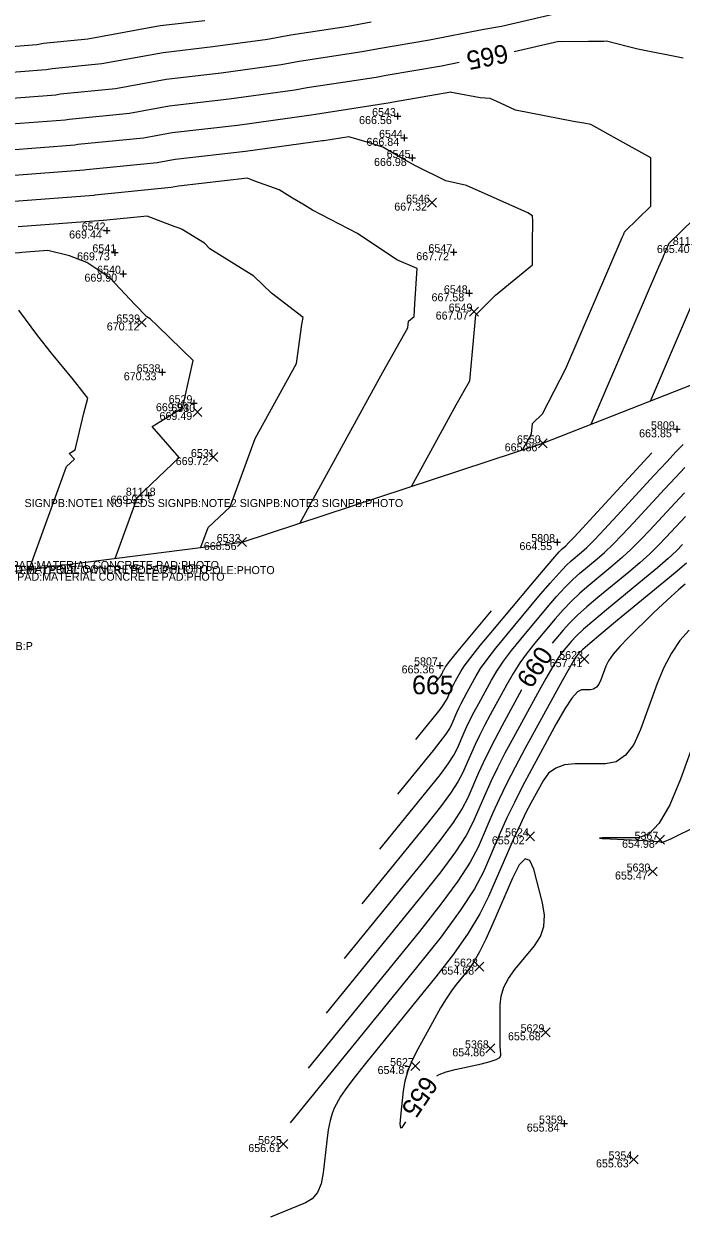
# Model space of a CAD drawing. Extents: x 2129350 to 2137777, y 657588 to 659885.
# Drawn here: x 2132634.9 to 2132733.5, y 658234.1 to 658413.1 of the extents above; entities that cross this region are included whole.
import ezdxf

# ---------------------------------------------------------------- set-up
doc = ezdxf.new("R2010")
doc.units = 0
for name, color, linetype in [('DT_X_Contour_Major', 7, 'Continuous'), ('DT_X_Contour_Minor', 7, 'Continuous'), ('DT_X_TIN_Hull', 7, 'Continuous'), ('SV_X_Random_Point', 7, 'Continuous'), ('SV_X_Shot_Marker', 7, 'Continuous'), ('SV_X_Text_Comment', 7, 'Continuous'), ('SV_X_Text_Elevation', 7, 'Continuous'), ('SV_X_Text_Name', 7, 'Continuous')]:
    doc.layers.add(name, color=color, linetype=linetype)

msp = doc.modelspace()

# ---------------------------------------------------------------- linework, layer by layer
at = {"layer": 'DT_X_Contour_Major'}
for points in [[(2132733.81, 658407.96), (2132726.98, 658409.33), (2132725.6, 658409.66), (2132722.3, 658410.53), (2132721.9, 658410.49), (2132719.6, 658410.48), (2132715.59, 658410.45), (2132715.13, 658410.49), (2132708.45, 658408.95)], [(2132700.21, 658407.32), (2132697.53, 658406.8), (2132689.22, 658405.37), (2132687.73, 658405.1), (2132677.4, 658403.51), (2132675.56, 658403.17), (2132665.7, 658401.82), (2132656.7, 658400.79), (2132650.73, 658399.69), (2132641.7, 658398.8), (2132641.1, 658398.69), (2132631.66, 658397.97), (2132623.7, 658396.59), (2132614.4, 658395.99), (2132605.99, 658395.57), (2132601.12, 658394.71)], [(2132720.02, 658353.06), (2132730.17, 658376.69), (2132730.64, 658377.78), (2132730.79, 658378.14), (2132730.92, 658378.42), (2132731, 658378.62), (2132731.05, 658378.74), (2132731.14, 658378.94), (2132731.18, 658379.03), (2132731.22, 658379.13), (2132731.27, 658379.25), (2132731.33, 658379.38), (2132731.49, 658379.76), (2132731.54, 658379.89), (2132731.58, 658379.98), (2132731.61, 658380.05), (2132731.63, 658380.08), (2132731.67, 658380.17), (2132737.35, 658385.73)], [(2132648.58, 658332.95), (2132651.92, 658342.14), (2132658.21, 658348.06), (2132654.14, 658352.71), (2132658.69, 658355.55), (2132658.89, 658356.35), (2132659.12, 658357.46), (2132660.29, 658362.61), (2132655, 658367.76), (2132653.85, 658368.86), (2132653.35, 658369.17), (2132651.55, 658371.01), (2132647.83, 658374.97), (2132647.18, 658375.42), (2132644.32, 658377.35), (2132641.75, 658378.31), (2132638.48, 658379.15), (2132634.61, 658378.85), (2132634.23, 658378.79), (2132620.68, 658377.91), (2132608.42, 658377.3), (2132606.2, 658376.91), (2132603.7, 658376.78)], [(2132734.14, 658339.24), (2132731.27, 658336.11), (2132730.11, 658334.91), (2132728.78, 658333.64), (2132727.29, 658332.3), (2132725.63, 658330.9), (2132720.98, 658327.07), (2132719.35, 658325.69), (2132717.95, 658324.42), (2132716.77, 658323.25), (2132715.82, 658322.2), (2132714.17, 658320.22)], [(2132696.36, 658313.97), (2132697.16, 658314.97), (2132697.32, 658315.16), (2132697.44, 658315.33), (2132697.53, 658315.47), (2132697.59, 658315.58), (2132697.7, 658315.83), (2132697.74, 658315.93), (2132697.8, 658316.04), (2132697.86, 658316.16), (2132697.93, 658316.29), (2132698.13, 658316.66), (2132698.33, 658316.94), (2132698.76, 658317.48), (2132699.42, 658318.29), (2132700.32, 658319.37), (2132705.07, 658325.06)], [(2132709.56, 658313.21), (2132706.6, 658307.79), (2132705.53, 658305.78), (2132704.59, 658303.95), (2132703.78, 658302.29), (2132703.11, 658300.8), (2132701.49, 658297.04), (2132700.63, 658295.41), (2132699.28, 658293.33), (2132697.42, 658290.81), (2132695.07, 658287.84), (2132682.92, 658272.93)], [(2132737.66, 658311.57), (2132733.4, 658299.82), (2132731.8, 658295.96), (2132730.21, 658293.21), (2132728.63, 658291.56), (2132727.05, 658291.01), (2132722.85, 658291.02), (2132721.66, 658291.01), (2132721.27, 658290.98), (2132721.67, 658290.93), (2132722.86, 658290.87), (2132727.09, 658290.66), (2132728.49, 658290.59), (2132729.51, 658290.53), (2132730.15, 658290.48), (2132730.41, 658290.44), (2132730.62, 658290.35), (2132730.99, 658290.47), (2132731.93, 658290.89), (2132733.45, 658291.61), (2132735.56, 658292.64)], [(2132711.38, 658286.31), (2132710.81, 658287.65), (2132710.09, 658287.88), (2132709.21, 658286.99), (2132708.19, 658284.99), (2132705.24, 658278.18), (2132704.19, 658275.83), (2132703.24, 658273.91), (2132702.38, 658272.42), (2132701.63, 658271.34), (2132699.76, 658269.05), (2132699.03, 658268.08), (2132698.24, 658266.9), (2132697.4, 658265.51), (2132696.49, 658263.91), (2132693.99, 658259.35), (2132693.15, 658257.67), (2132692.51, 658256.07), (2132692.06, 658254.53), (2132691.8, 658253.07), (2132691.37, 658249.25), (2132691.29, 658248.1), (2132691.37, 658247.54), (2132691.62, 658247.57), (2132692.03, 658248.17), (2132692.19, 658248.45)], [(2132696.84, 658255.36), (2132697.19, 658255.55), (2132698.24, 658255.94), (2132699.59, 658256.29), (2132703.55, 658257.15), (2132704.84, 658257.47), (2132705.76, 658257.79), (2132706.3, 658258.11), (2132706.46, 658258.42), (2132706.39, 658259.26), (2132706.36, 658259.69), (2132706.35, 658260.38), (2132706.34, 658261.31), (2132706.34, 658262.49), (2132706.36, 658265.98), (2132706.5, 658267.29), (2132706.92, 658268.61), (2132707.61, 658269.93), (2132708.57, 658271.26), (2132711.5, 658274.81), (2132712.4, 658276.21), (2132712.9, 658277.75), (2132713, 658279.43), (2132712.7, 658281.26), (2132711.38, 658286.31)]]:
    msp.add_lwpolyline(points, dxfattribs=at)
at = {"layer": 'DT_X_Contour_Minor'}
for points in [[(2132686.97, 658413.36), (2132683.52, 658412.74), (2132674.93, 658411.42), (2132671.43, 658410.78), (2132663.25, 658409.66), (2132655.79, 658408.8), (2132646.57, 658407.11), (2132639.12, 658406.37), (2132638.25, 658406.21), (2132630.49, 658405.62), (2132619.48, 658403.71), (2132611.89, 658403.22), (2132605.01, 658402.87), (2132595.15, 658401.13), (2132587.26, 658400.74), (2132586.04, 658400.5), (2132584.46, 658400.12), (2132577.38, 658399.83), (2132558.94, 658412.26), (2132549.46, 658417.46)], [(2132714.5, 658414.57), (2132706.55, 658412.74), (2132703.92, 658412.27), (2132695.72, 658410.68), (2132688.1, 658409.36), (2132685.62, 658408.92), (2132676.17, 658407.46), (2132673.49, 658406.97), (2132664.48, 658405.74), (2132656.25, 658404.8), (2132648.65, 658403.4), (2132640.41, 658402.58), (2132639.67, 658402.45), (2132631.07, 658401.8), (2132621.59, 658400.15), (2132613.14, 658399.61), (2132605.5, 658399.22), (2132596.73, 658397.67), (2132587.92, 658397.23), (2132586.82, 658397.02), (2132585.4, 658396.68), (2132577.49, 658396.35), (2132556.9, 658410.23), (2132546.31, 658416.04)], [(2132662.03, 658413.58), (2132655.34, 658412.81), (2132644.48, 658410.82), (2132637.83, 658410.16), (2132636.83, 658409.97), (2132629.9, 658409.45), (2132617.38, 658407.27), (2132610.63, 658406.84), (2132604.53, 658406.53), (2132593.57, 658404.59), (2132586.59, 658404.24), (2132585.26, 658403.98), (2132583.52, 658403.57), (2132577.26, 658403.31), (2132560.98, 658414.29)], [(2132709.71, 658349.21), (2132710.75, 658351.1), (2132711.06, 658351.65), (2132711.2, 658353.17), (2132712.68, 658354.65), (2132716.22, 658361.42), (2132724.67, 658381.09), (2132724.79, 658381.36), (2132724.83, 658381.46), (2132724.86, 658381.53), (2132724.89, 658381.58), (2132724.9, 658381.61), (2132724.92, 658381.66), (2132724.93, 658381.68), (2132724.94, 658381.71), (2132724.95, 658381.74), (2132724.97, 658381.77), (2132725.01, 658381.87), (2132725.02, 658381.9), (2132725.04, 658381.93), (2132725.04, 658381.95), (2132725.05, 658381.95), (2132725.06, 658381.98), (2132728.94, 658385.77), (2132728.94, 658388.15), (2132728.94, 658393.01), (2132724.35, 658395.57), (2132719.96, 658398.05), (2132718.92, 658398.21), (2132717.35, 658398.46), (2132708.67, 658400.16), (2132706.38, 658401.24), (2132704.87, 658401.91), (2132703.34, 658402.04), (2132699.62, 658402.72), (2132699.1, 658402.82), (2132698.96, 658402.86), (2132690.34, 658401.37), (2132689.83, 658401.28), (2132678.64, 658399.55), (2132677.62, 658399.37), (2132666.93, 658397.9), (2132657.16, 658396.78), (2132652.82, 658395.99), (2132642.98, 658395.01), (2132642.52, 658394.92), (2132632.25, 658394.15)], [(2132693.02, 658343.74), (2132699.75, 658355.98), (2132701.78, 658359.58), (2132702.69, 658369.46), (2132705.66, 658372.44), (2132711.18, 658377), (2132711.2, 658377.63), (2132711.2, 658380.22), (2132711.23, 658383.54), (2132711.22, 658384.34), (2132710.5, 658384.77), (2132701.32, 658388.88), (2132698.19, 658389.59), (2132693.64, 658391.85), (2132692.2, 658392.62), (2132691.82, 658392.84), (2132688.74, 658394.65), (2132686.37, 658395.39), (2132683.62, 658396.18), (2132679.87, 658395.6), (2132679.69, 658395.56), (2132668.15, 658393.99), (2132657.61, 658392.78), (2132654.9, 658392.28), (2132644.27, 658391.22), (2132643.94, 658391.16), (2132632.84, 658390.33)], [(2132676.33, 658338.26), (2132688.76, 658360.87), (2132692.5, 658367.51), (2132692.6, 658368.55), (2132693.45, 658369.23), (2132693.52, 658371.12), (2132693.9, 658376.44), (2132690.83, 658377.75), (2132684.92, 658381.69), (2132678.21, 658385.19), (2132676.74, 658386.06), (2132675.19, 658386.97), (2132673.21, 658388.21), (2132669.56, 658389.52), (2132668.43, 658389.96), (2132658.07, 658388.77), (2132656.98, 658388.57), (2132645.56, 658387.44), (2132645.37, 658387.4), (2132633.43, 658386.5)], [(2132661.46, 658334.61), (2132662.54, 658337.58), (2132665.84, 658340.68), (2132669.59, 658350.94), (2132675.77, 658362.17), (2132676.6, 658368.01), (2132676.79, 658369.08), (2132672.06, 658372.72), (2132669.39, 658375.27), (2132662.78, 658379.4), (2132661.99, 658380.21), (2132658.65, 658382.26), (2132658.34, 658382.45), (2132657.46, 658382.75), (2132653.38, 658384.3), (2132646.84, 658383.65), (2132646.79, 658383.64), (2132634.02, 658382.68)], [(2132728.9, 658356.55), (2132735.67, 658372.3)], [(2132635.7, 658331.3), (2132641.3, 658346.71), (2132642.47, 658347.81), (2132641.71, 658348.68), (2132642.57, 658349.21), (2132643.91, 658354.74), (2132644.51, 658356.99), (2132642.35, 658359.71), (2132639.06, 658363.74), (2132636.97, 658366.32), (2132634.12, 658370.2)], [(2132690.98, 658297.56), (2132696.33, 658304.11), (2132697.36, 658305.42), (2132698.18, 658306.53), (2132698.77, 658307.45), (2132699.15, 658308.16), (2132699.86, 658309.81), (2132700.16, 658310.47), (2132700.52, 658311.2), (2132700.93, 658312.01), (2132701.4, 658312.89), (2132702.74, 658315.34), (2132703.4, 658316.41), (2132704.39, 658317.8), (2132705.71, 658319.49), (2132707.35, 658321.5), (2132712.17, 658327.26), (2132713.83, 658329.21), (2132715.18, 658330.75), (2132716.23, 658331.86), (2132716.98, 658332.56), (2132718.56, 658333.86), (2132719.34, 658334.57), (2132720.49, 658335.73), (2132722.01, 658337.33), (2132723.91, 658339.37), (2132729.46, 658345.41), (2132731.33, 658347.43), (2132732.77, 658348.97), (2132733.79, 658350.02)], [(2132693.67, 658305.77), (2132696.74, 658309.54), (2132697.34, 658310.29), (2132697.81, 658310.93), (2132698.15, 658311.46), (2132698.37, 658311.87), (2132698.78, 658312.82), (2132698.95, 658313.2), (2132699.16, 658313.62), (2132699.39, 658314.08), (2132699.67, 658314.59), (2132700.43, 658316), (2132700.95, 658316.78), (2132701.93, 658318.07), (2132703.37, 658319.86), (2132705.27, 658322.15), (2132710.96, 658328.95), (2132712.85, 658331.2), (2132714.26, 658332.85), (2132715.19, 658333.92), (2132715.64, 658334.39), (2132716.2, 658334.85), (2132716.62, 658335.26), (2132717.45, 658336.13), (2132718.7, 658337.46), (2132720.36, 658339.27), (2132729.09, 658348.76)], [(2132688.29, 658289.35), (2132695.91, 658298.69), (2132697.38, 658300.55), (2132698.54, 658302.13), (2132699.39, 658303.43), (2132699.93, 658304.46), (2132700.95, 658306.81), (2132701.37, 658307.74), (2132701.87, 658308.79), (2132702.46, 658309.93), (2132703.13, 658311.19), (2132705.04, 658314.68), (2132705.85, 658316.04), (2132706.85, 658317.53), (2132708.05, 658319.13), (2132709.43, 658320.84), (2132713.39, 658325.57), (2132714.81, 658327.23), (2132716.1, 658328.64), (2132717.27, 658329.8), (2132718.31, 658330.73), (2132720.92, 658332.87), (2132721.99, 658333.82), (2132723.25, 658335.03), (2132724.71, 658336.52), (2132726.36, 658338.28), (2132731.02, 658343.35), (2132732.65, 658345.1), (2132734.05, 658346.56)], [(2132733.98, 658342.78), (2132732.58, 658341.29), (2132728.82, 658337.2), (2132727.41, 658335.72), (2132726.02, 658334.34), (2132724.64, 658333.06), (2132723.27, 658331.89), (2132719.65, 658328.9), (2132718.31, 658327.75), (2132717.03, 658326.53), (2132715.79, 658325.24), (2132714.61, 658323.89), (2132711.51, 658320.19), (2132710.38, 658318.76), (2132709.31, 658317.26), (2132708.3, 658315.68), (2132707.34, 658314.02), (2132704.87, 658309.49), (2132704, 658307.86), (2132703.23, 658306.37), (2132702.58, 658305.02), (2132702.03, 658303.8), (2132700.71, 658300.75), (2132700.01, 658299.42), (2132698.91, 658297.73), (2132697.4, 658295.68), (2132695.49, 658293.26), (2132685.6, 658281.14)], [(2132733.72, 658335.03), (2132732.81, 658334.1), (2132731.55, 658332.94), (2132729.94, 658331.55), (2132727.99, 658329.91), (2132722.32, 658325.24), (2132720.39, 658323.63), (2132718.87, 658322.31), (2132717.76, 658321.27), (2132717.04, 658320.51), (2132715.67, 658318.88), (2132715.05, 658318.03), (2132714.23, 658316.72), (2132713.19, 658314.94), (2132711.94, 658312.69), (2132708.34, 658306.09), (2132707.07, 658303.71), (2132705.95, 658301.53), (2132704.99, 658299.56), (2132704.19, 658297.79), (2132702.27, 658293.34), (2132701.25, 658291.4), (2132699.64, 658288.93), (2132697.44, 658285.94), (2132694.65, 658282.41), (2132680.23, 658264.72)], [(2132734.31, 658332.25), (2132732.59, 658330.79), (2132730.35, 658328.92), (2132723.66, 658323.41), (2132721.44, 658321.58), (2132719.8, 658320.2), (2132718.74, 658319.28), (2132718.26, 658318.83), (2132717.75, 658318.22), (2132717.39, 658317.67), (2132716.69, 658316.45), (2132715.64, 658314.57), (2132714.24, 658312.03), (2132710.07, 658304.39), (2132708.6, 658301.63), (2132707.31, 658299.12), (2132706.2, 658296.83), (2132705.27, 658294.78), (2132703.05, 658289.63), (2132701.87, 658287.39), (2132700.01, 658284.54), (2132697.46, 658281.07), (2132694.23, 658276.99), (2132677.54, 658256.51)], [(2132734.1, 658329.09), (2132733.1, 658328.24), (2132731.98, 658327.23), (2132730.74, 658326.07), (2132729.37, 658324.76), (2132725.57, 658321.05), (2132724.29, 658319.74), (2132723.3, 658318.59), (2132722.6, 658317.6), (2132722.18, 658316.76), (2132721.45, 658314.75), (2132721.14, 658314.09), (2132720.78, 658313.62), (2132720.37, 658313.33), (2132719.9, 658313.24), (2132718.57, 658313.24), (2132717.95, 658312.92), (2132717.12, 658311.96), (2132716.06, 658310.36), (2132714.77, 658308.12), (2132711.05, 658301.29), (2132709.71, 658298.78), (2132708.48, 658296.35), (2132707.36, 658294.02), (2132706.36, 658291.78), (2132703.83, 658285.92), (2132702.49, 658283.38), (2132700.37, 658280.14), (2132697.48, 658276.2), (2132693.81, 658271.56), (2132674.85, 658248.3)], [(2132734.72, 658322.18), (2132733.32, 658320.61), (2132732.06, 658318.75), (2132730.92, 658316.6), (2132729.92, 658314.16), (2132727.42, 658307.28), (2132726.39, 658305.02), (2132725.16, 658303.41), (2132723.75, 658302.45), (2132722.14, 658302.13), (2132717.58, 658302.13), (2132716, 658301.98), (2132714.68, 658301.5), (2132713.61, 658300.71), (2132712.79, 658299.6), (2132710.94, 658296.22), (2132710.21, 658294.81), (2132709.38, 658293.09), (2132708.45, 658291.08), (2132707.44, 658288.77), (2132704.61, 658282.22), (2132703.31, 658279.62), (2132701.56, 658276.74), (2132699.35, 658273.59), (2132696.67, 658270.17), (2132688.92, 658260.65), (2132686.33, 658257.45), (2132684.38, 658254.98), (2132683.07, 658253.24), (2132682.4, 658252.23), (2132681.45, 658250.5), (2132681.12, 658249.71), (2132680.82, 658248.62), (2132680.56, 658247.25), (2132680.34, 658245.6), (2132679.8, 658240.79), (2132679.48, 658239.16), (2132678.93, 658237.86), (2132678.15, 658236.9), (2132677.14, 658236.27), (2132671.88, 658234.14)]]:
    msp.add_lwpolyline(points, dxfattribs=at)
at = {"layer": 'DT_X_TIN_Hull'}
msp.add_lwpolyline([(2132540.53, 658289.4), (2132539.03, 658286.06), (2132536.83, 658279.3), (2132537.2, 658279.01), (2132540.62, 658270.42), (2132548.2, 658269.84), (2132579.39, 658310.87), (2132621, 658329.41), (2132667.62, 658335.4), (2132712.75, 658350.21), (2132765.51, 658370.93), (2132811.12, 658416.76), (2132865.06, 658421.38), (2132884.19, 658431.34), (2132933.33, 658488.43), (2132983.35, 658480.41), (2133063.13, 658518.41), (2133131.97, 658559.41), (2133180.89, 658556.24), (2133241.37, 658575.53)], dxfattribs=at)
at = {"layer": 'SV_X_Random_Point'}
for p, q in [((2132695.44, 658385.65), (2132696.77, 658386.98)), ((2132695.44, 658386.98), (2132696.77, 658385.65)), ((2132701.76, 658369.3), (2132703.09, 658370.64)), ((2132701.76, 658370.64), (2132703.09, 658369.3)), ((2132651.91, 658367.66), (2132653.25, 658369)), ((2132651.91, 658369), (2132653.25, 658367.66)), ((2132660.27, 658354.24), (2132661.6, 658355.58)), ((2132660.27, 658355.58), (2132661.6, 658354.24)), ((2132712.08, 658349.54), (2132713.42, 658350.88)), ((2132712.08, 658350.88), (2132713.42, 658349.54)), ((2132662.66, 658347.47), (2132663.99, 658348.81)), ((2132662.66, 658348.81), (2132663.99, 658347.47)), ((2132666.95, 658334.73), (2132668.29, 658336.07)), ((2132666.95, 658336.07), (2132668.29, 658334.73)), ((2132718.3, 658317.17), (2132719.64, 658318.51)), ((2132718.3, 658318.51), (2132719.64, 658317.17)), ((2132710.18, 658290.59), (2132711.51, 658291.92)), ((2132710.18, 658291.92), (2132711.51, 658290.59)), ((2132729.65, 658290.07), (2132730.98, 658291.41)), ((2132729.65, 658291.41), (2132730.98, 658290.07)), ((2132728.55, 658285.31), (2132729.88, 658286.65)), ((2132728.55, 658286.65), (2132729.88, 658285.31)), ((2132702.54, 658271.05), (2132703.88, 658272.39)), ((2132702.54, 658272.39), (2132703.88, 658271.05)), ((2132712.52, 658261.2), (2132713.85, 658262.54)), ((2132712.52, 658262.54), (2132713.85, 658261.2)), ((2132704.22, 658258.79), (2132705.56, 658260.13)), ((2132704.22, 658260.13), (2132705.56, 658258.79)), ((2132692.93, 658256.14), (2132694.27, 658257.47)), ((2132692.93, 658257.47), (2132694.27, 658256.14)), ((2132673.14, 658244.43), (2132674.47, 658245.77)), ((2132673.14, 658245.77), (2132674.47, 658244.43)), ((2132725.71, 658242.13), (2132727.05, 658243.46)), ((2132725.71, 658243.46), (2132727.05, 658242.13))]:
    msp.add_line(p, q, dxfattribs=at)
at = {"layer": 'SV_X_Shot_Marker'}
for p, q in [((2132690.43, 658399.29), (2132691.43, 658399.29)), ((2132690.93, 658399.79), (2132690.93, 658398.79)), ((2132690.93, 658399.29), (2132690.93, 658399.29)), ((2132691.46, 658396.02), (2132692.46, 658396.02)), ((2132691.96, 658396.52), (2132691.96, 658395.52)), ((2132691.96, 658396.02), (2132691.96, 658396.02)), ((2132692.62, 658393.01), (2132693.62, 658393.01)), ((2132693.12, 658393.51), (2132693.12, 658392.51)), ((2132693.12, 658393.01), (2132693.12, 658393.01)), ((2132646.86, 658382.13), (2132647.86, 658382.13)), ((2132647.36, 658382.63), (2132647.36, 658381.63)), ((2132647.36, 658382.13), (2132647.36, 658382.13)), ((2132648.03, 658378.85), (2132649.03, 658378.85)), ((2132648.53, 658379.35), (2132648.53, 658378.35)), ((2132648.53, 658378.85), (2132648.53, 658378.85)), ((2132698.87, 658378.87), (2132699.87, 658378.87)), ((2132699.37, 658379.37), (2132699.37, 658378.37)), ((2132699.37, 658378.87), (2132699.37, 658378.87)), ((2132649.78, 658376.15), (2132649.78, 658375.15)), ((2132649.28, 658375.65), (2132650.28, 658375.65)), ((2132649.78, 658375.65), (2132649.78, 658375.65)), ((2132701.21, 658372.71), (2132702.21, 658372.71)), ((2132701.71, 658373.21), (2132701.71, 658372.21)), ((2132701.71, 658372.71), (2132701.71, 658372.71)), ((2132655.13, 658360.86), (2132656.13, 658360.86)), ((2132655.63, 658361.36), (2132655.63, 658360.36)), ((2132655.63, 658360.86), (2132655.63, 658360.86)), ((2132659.89, 658356.22), (2132660.89, 658356.22)), ((2132660.39, 658356.72), (2132660.39, 658355.72)), ((2132660.39, 658356.22), (2132660.39, 658356.22)), ((2132732.87, 658352.81), (2132732.87, 658351.81)), ((2132732.37, 658352.31), (2132733.37, 658352.31)), ((2132732.87, 658352.31), (2132732.87, 658352.31)), ((2132653.09, 658342.36), (2132654.09, 658342.36)), ((2132653.59, 658342.86), (2132653.59, 658341.86)), ((2132653.59, 658342.36), (2132653.59, 658342.36)), ((2132714.41, 658335.39), (2132715.41, 658335.39)), ((2132714.91, 658335.89), (2132714.91, 658334.89)), ((2132714.91, 658335.39), (2132714.91, 658335.39)), ((2132696.81, 658316.9), (2132697.81, 658316.9)), ((2132697.31, 658317.4), (2132697.31, 658316.4)), ((2132697.31, 658316.9), (2132697.31, 658316.9)), ((2132715.47, 658248.17), (2132716.47, 658248.17)), ((2132715.97, 658248.67), (2132715.97, 658247.67)), ((2132715.97, 658248.17), (2132715.97, 658248.17))]:
    msp.add_line(p, q, dxfattribs=at)

# ---------------------------------------------------------------- texts
at = {"layer": 'DT_X_Contour_Major'}
for s, rotation, p in [('665', 191.2107, (2132707.23, 658410.13)), ('660', 56.6951, (2132711.01, 658313.27)), ('655', 236.0775, (2132694.88, 658255.56))]:
    msp.add_text(s, height=2.8, rotation=rotation, dxfattribs=at).set_placement(p)
msp.add_text('665', height=2.8, dxfattribs=at).set_placement((2132693.13, 658312.57))
at = {"layer": 'SV_X_Text_Comment'}
for s, p in [('SIGNPB:NOTE1 NO PEDS SIGNPB:NOTE2 SIGNPB:NOTE3 SIGNPB:PHOTO', (2132634.99, 658340.65)), ('PAD:NOTE LPOLE PAD:MATERIAL CONCRETE PAD:PHOTO', (2132617.19, 658330.73)), ('LPOLE:MATERIAL STEEL LPOLE:OWNER LPOLE:POLE# LPOLE:PHOTO', (2132618.12, 658330.59)), ('PAD:NOTE LPOLE PAD:MATERIAL CONCRETE PAD:PHOTO', (2132618.78, 658331.36)), ('PAD:NOTE LPOLE PAD:MATERIAL CONCRETE PAD:PHOTO', (2132619.62, 658329.6)), ('2-2B CB-2-2B:P1 CB-2-2B:P2 CB-2-2B:P3 CB-2-2B:P4 CB-2-2B:P5 CB-2-2B:N5 CB-2-2B:P', (2132570.6, 658319.21))]:
    msp.add_text(s, height=1.2, dxfattribs=at).set_placement(p)
at = {"layer": 'SV_X_Text_Elevation'}
for s, p in [('666.56', (2132685.18, 658398.09)), ('666.84', (2132686.29, 658394.82)), ('666.98', (2132687.42, 658391.81)), ('667.32', (2132690.46, 658385.11)), ('669.44', (2132641.68, 658380.93)), ('665.40', (2132729.86, 658378.75)), ('669.73', (2132642.87, 658377.65)), ('667.72', (2132693.76, 658377.67)), ('669.90', (2132643.98, 658374.45)), ('667.58', (2132696.05, 658371.51)), ('667.07', (2132696.67, 658368.77)), ('670.12', (2132647.33, 658367.13)), ('670.33', (2132649.88, 658359.66)), ('669.94', (2132654.7, 658355.02)), ('669.49', (2132655.24, 658353.71)), ('663.85', (2132727.19, 658351.11)), ('665.86', (2132707.02, 658349.01)), ('669.72', (2132657.67, 658346.94)), ('669.93', (2132647.89, 658341.16)), ('668.56', (2132661.89, 658334.2)), ('664.55', (2132709.24, 658334.19)), ('665.36', (2132691.56, 658315.7)), ('657.41', (2132713.77, 658316.64)), ('655.02', (2132705.1, 658290.06)), ('654.98', (2132724.63, 658289.54)), ('655.47', (2132723.57, 658284.78)), ('654.68', (2132697.53, 658270.52)), ('655.68', (2132707.52, 658260.67)), ('654.86', (2132699.17, 658258.26)), ('654.87', (2132687.95, 658255.6)), ('655.84', (2132710.34, 658246.97)), ('656.61', (2132668.56, 658243.9)), ('655.63', (2132720.72, 658241.6))]:
    msp.add_text(s, height=1.2, dxfattribs=at).set_placement(p)
at = {"layer": 'SV_X_Text_Name'}
for s, p in [('6543', (2132687.13, 658399.29)), ('6544', (2132688.17, 658396.02)), ('6545', (2132689.32, 658393.01)), ('6546', (2132692.23, 658386.31)), ('6542', (2132643.57, 658382.13)), ('6541', (2132645.17, 658378.85)), ('6547', (2132695.58, 658378.87)), ('81119', (2132732.24, 658379.95)), ('6540', (2132645.88, 658375.65)), ('6548', (2132697.9, 658372.71)), ('6549', (2132698.62, 658369.97)), ('6539', (2132648.76, 658368.33)), ('6538', (2132651.81, 658360.86)), ('6529', (2132656.61, 658356.22)), ('6530', (2132657.02, 658354.91)), ('5809', (2132728.97, 658352.31)), ('6550', (2132708.86, 658350.21)), ('6531', (2132659.95, 658348.14)), ('81118', (2132650.19, 658342.36)), ('6532', (2132663.82, 658335.4)), ('5808', (2132711.01, 658335.39)), ('5623', (2132715.2, 658317.84)), ('5807', (2132693.43, 658316.9)), ('5624', (2132707.08, 658291.26)), ('5367', (2132726.5, 658290.74)), ('5630', (2132725.31, 658285.98)), ('5628', (2132699.43, 658271.72)), ('5629', (2132709.41, 658261.87)), ('5368', (2132701.07, 658259.46)), ('5627', (2132689.83, 658256.8)), ('5359', (2132712.17, 658248.17)), ('5625', (2132670.03, 658245.1)), ('5354', (2132722.6, 658242.8))]:
    msp.add_text(s, height=1.2, dxfattribs=at).set_placement(p)

doc.saveas('drawing.dxf')
